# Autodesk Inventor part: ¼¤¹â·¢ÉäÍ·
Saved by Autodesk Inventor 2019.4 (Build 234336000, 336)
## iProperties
Created: 2020-05
Part Number: ¼¤¹â·¢ÉäÍ·
Material: Generic
Document SubType Name: Modeling
Designer: Administrator
Density: 1 g/cm^3
Appearance: Default
Title: ¼¤¹â·¢ÉäÍ·
Author: Administrator
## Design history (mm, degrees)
feature "Body1"
body "Solid1"
